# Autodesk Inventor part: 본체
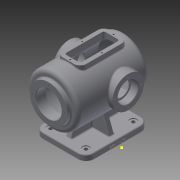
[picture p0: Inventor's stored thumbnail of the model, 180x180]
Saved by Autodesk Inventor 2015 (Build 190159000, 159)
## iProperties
Created: 2021-11
Part Number: 본체
Material: 일반
Document SubType Name: Modeling
Designer: now
Density: 1 g/cm^3
Appearance: 기본값
Author: now
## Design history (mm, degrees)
sketch "스케치1"
  geometry: L1 (-65, 80)-(65, 80); L2 (65, 80)-(65, -80); L3 (65, -80)-(-65, -80); L4 (-65, -80)-(-65, 80); L5 (-65, 80)-(65, -80); L6 (65, 80)-(-65, -80); 1 further point
  constraints: 12 end point, 2 midpoint, 2 parallel, 1 horizontal, 1 perpendicular
  dimensions: "d0" = 130 distance of L2.end L3.end; "d1" = 160 distance of L1.end L2.end
extrude "돌출1" new body sketch "스케치1" distance "d2" = 14; taper "d3" = 0 deg
fillet "모깎기1" dims "d4" = 20
sketch "스케치2"
  geometry: A1 r 20 centre (-45, 60) between (-45, 80) and (-65, 60) reference; A2 r 20 centre (-45, -60) between (-65, -60) and (-45, -80) reference; A3 r 20 centre (45, -60) between (45, -80) and (65, -60) reference; A4 r 20 centre (45, 60) between (65, 60) and (45, 80) reference; 1 further point
hole "구멍1" sketch "스케치2" at (-45, -60), (-45, 60), (45, 60), (45, -60) diameter "d5" = 9; stored, may be unused: countersink angle "d9" = 90 deg, drill point angle "d11" = 118 deg; dims "d6" = 6, "d7" = 18, "d8" = 2, "d10" = 8
fillet "모깎기2" dims "d12" = 3
sketch "스케치3"
  geometry: L1 (-7, -60)-(7, -60); L2 (7, -60)-(7, 60); L3 (7, 60)-(-7, 60); L4 (-7, 60)-(-7, -60); L5 (-7, -60)-(7, 60); L6 (7, -60)-(-7, 60); L7 (-50, 7)-(50, 7); L8 (50, 7)-(50, -7); L9 (50, -7)-(-50, -7); L10 (-50, -7)-(-50, 7); L11 (-50, 7)-(50, -7); L12 (50, 7)-(-50, -7); 1 further point
  constraints: 24 end point, 4 midpoint, 4 parallel, 2 horizontal, 2 perpendicular
  dimensions: "d13" = 120 distance of L1.end L2.end; "d14" = 14 distance of L1.start L1.end; "d15" = 14 distance of L7.end L8.end; "d16" = 100 distance of L8.end L9.end
extrude "돌출2" join sketch "스케치3" distance "d17" = 100; taper "d18" = 0 deg
feature "면 기울기1" dims angle "d19" = 20 deg
feature "면 기울기2" dims angle "d20" = 20 deg
fillet "모깎기3" dims "d21" = 3
fillet "모깎기4" dims "d22" = 3
sketch "스케치4"
  geometry: L1 (62.101, 14)-(77, 14) reference; L2 (80, 11)-(80, 0) reference; L3 (80, 0)-(-80, 0) reference; L4 (-80, 0)-(-80, 11) reference; L5 (-77, 14)-(-62.101, 14) reference; L6 (-59.282, 15.974)-(-23.603, 114) reference; L7 (-23.603, 114)-(23.603, 114) reference; L8 (23.603, 114)-(59.282, 15.974) reference; L9 (100, 114)-(-100, 114); L10 (-100, 114)-(-100, 179); L11 (-100, 179)-(100, 114); L12 (99.021, 184.824)-(-100, 114); L13 (-100, 179)-(75.993, 179); A1 r 3 centre (62.101, 17) between (59.282, 15.974) and (62.101, 14) reference; A2 r 3 centre (77, 11) between (80, 11) and (77, 14) reference; A3 r 3 centre (-77, 11) between (-77, 14) and (-80, 11) reference; A4 r 3 centre (-62.101, 17) between (-62.101, 14) and (-59.282, 15.974) reference; A5 r 100 centre (0, 114) between (100, 114) and (75.993, 179); 2 further points
  constraints: 10 end point, 2 point on circle, 2 point on line, 1 centre point, 1 horizontal
  dimensions: "d23" = 20 distance between parallel lines of L4 L10; "d26" = 114 distance between parallel lines of L9 L3; "d28" = 200 distance from line of L9.start L10; "d37" = 65 distance between parallel lines of L13 L9; "d38" = 175.99342 distance of L10.end L13.end; "d39" = 100 radius of A5
revolve "회전1" sketch "스케치4" stored, may be unused: angle "d32" = 90 deg
sketch "스케치5"
  geometry: C1 r 65 at (0, 0) reference; C2 r 47.5 at (0, 0); 1 further point
  constraints: 1 centre point, 1 coincident
  dimensions: "d33" = 95 diameter of C2
extrude "돌출3" join sketch "스케치5" distance "d34" = 10; taper "d35" = 0 deg
sketch "스케치6"
  geometry: C1 r 47.5 at (0, 0) reference; 1 further point
hole "구멍2" sketch "스케치6" at (0, 0) diameter "d40" = 65; stored, may be unused: countersink angle "d44" = 90 deg, drill point angle "d46" = 0 deg; dims "d41" = 6, "d42" = 4, "d43" = 2, "d45" = 25
chamfer "모따기1" distance "d47" = 1; stored, may be unused: second distance "d48" = 2, angle "d49" = 45 deg
sketch "스케치7"
  geometry: L1 (62.101, 14)-(77, 14) reference; L2 (80, 11)-(80, 0) reference; L3 (80, 0)-(-80, 0) reference; L4 (-80, 0)-(-80, 11) reference; L5 (-77, 14)-(-62.101, 14) reference; L6 (-59.282, 15.974)-(-47.261, 49) reference; L7 (-47.261, 49)-(-100, 49) reference; L8 (-100, 49)-(-100, 66.5) reference; L9 (-100, 66.5)-(-110, 66.5) reference; L10 (-110, 66.5)-(-110, 80.5) reference; L11 (-110, 80.5)-(-109, 81.5) reference; L12 (-109, 81.5)-(-85, 81.5) reference; L13 (-85, 81.5)-(-85, 146.5) reference; L14 (-85, 146.5)-(-109, 146.5) reference; L15 (-109, 146.5)-(-110, 147.5) reference; L16 (-110, 147.5)-(-110, 161.5) reference; L17 (-110, 161.5)-(-100, 161.5) reference; L18 (-100, 161.5)-(-100, 179) reference; L19 (-100, 179)-(75.993, 179) reference; L20 (75.993, 49)-(47.261, 49) reference; L21 (47.261, 49)-(59.282, 15.974) reference; L22 (-85, 169)-(71.239, 169); L23 (-85, 146.5)-(-85, 81.5) reference; L24 (-85, 114)-(90, 114); L25 (-85, 169)-(-85, 114); A1 r 3 centre (62.101, 17) between (59.282, 15.974) and (62.101, 14) reference; A2 r 3 centre (77, 11) between (80, 11) and (77, 14) reference; A3 r 3 centre (-77, 11) between (-77, 14) and (-80, 11) reference; A4 r 3 centre (-62.101, 17) between (-62.101, 14) and (-59.282, 15.974) reference; A5 r 100 centre (0, 114) between (75.993, 49) and (75.993, 179) reference; A6 r 90 centre (0, 114) between (90, 114) and (71.239, 169); 2 further points
  constraints: 6 end point, 2 midpoint, 2 point on circle, 1 centre point, 1 perpendicular, 1 vertical alignment
  dimensions: "d50" = 156.23903 distance of L22.start L22.end; "d51" = 55 distance of L22.start L24.start; "d52" = 175 distance of L24.start L24.end; "d53" = 90 radius of A6
revolve "회전2" sketch "스케치7" stored, may be unused: angle "d54" = 90 deg
fillet "모깎기5" dims "d55" = 3
fillet "모깎기6" dims "d56" = 10
sketch "스케치8"
  geometry: C1 r 47.5 at (0, 0) reference; 2 further points
  constraints: 1 vertical alignment
  dimensions: "d57" = 40 distance of C1.centre point (0, 40)
hole "구멍3" sketch "스케치8" at (0, 40) diameter "d58" = 3.242; stored, may be unused: countersink angle "d62" = 90 deg, drill point angle "d64" = 118 deg; dims "d59" = 11, "d60" = 4, "d61" = 2, "d63" = 13
node "작업 평면1"
sketch "스케치9"
  geometry: L1 (30, -60)-(-30, -60); L2 (-30, -60)-(-30, 60); L3 (-30, 60)-(30, 60); L4 (30, 60)-(30, -60); L5 (30, -60)-(-30, 60); L6 (-30, -60)-(30, 60); L7 (-47.5, -110)-(47.5, -110) reference; 4 further points
  constraints: 12 end point, 4 midpoint, 2 parallel, 1 horizontal, 1 perpendicular, 1 vertical alignment
  dimensions: "d69" = 120 distance of L3.end L1.start; "d70" = 50 distance between parallel lines of L1 L7; "d71" = 60 distance of L1.start L1.end
extrude "돌출4" join sketch "스케치9" stored distance "d72" = 10; taper "d73" = 0 deg
sketch "스케치10"
  geometry: L1 (-20, -50)-(20, -50); L2 (20, -50)-(20, 50); L3 (20, 50)-(-20, 50); L4 (-20, 50)-(-20, -50); 1 further point
  constraints: 8 end point
extrude "돌출5" cut sketch "스케치10" distance "d74" = 47.5; taper "d75" = 0 deg
fillet "모깎기7" dims "d76" = 15
fillet "모깎기8" dims "d77" = 5
fillet "모깎기9" dims "d78" = 3
fillet "모깎기10" dims "d79" = 3
sketch "스케치11"
  geometry: 2 further points
  constraints: 1 horizontal alignment
  dimensions: "d80" = 25 distance of point (-25, 0) point (0, 0)
hole "구멍4" sketch "스케치11" at (-25, 0) diameter "d81" = 3.242; stored, may be unused: countersink angle "d85" = 90 deg, drill point angle "d87" = 118 deg; dims "d82" = 9, "d83" = 4, "d84" = 2, "d86" = 11
sketch "스케치12"
  geometry: 2 further points
  constraints: 1 vertical alignment
  dimensions: "d88" = 55 distance of point (0, 0) point (0, -55)
hole "구멍5" sketch "스케치12" at (0, -55) diameter "d89" = 3.242; stored, may be unused: countersink angle "d93" = 90 deg, drill point angle "d95" = 118 deg; dims "d90" = 9, "d91" = 4, "d92" = 2, "d94" = 11
node "작업 평면2"
node "작업 평면3"
sketch "스케치13"
  geometry: 1 further point
sketch "스케치14"
  geometry: L1 (60, 0)-(-60, 0) reference; C1 r 40 at (17, 114); 1 further point
  constraints: 1 centre point
  dimensions: "d98" = 17 horizontal distance of point (0, 0) C1.centre; "d99" = 80 diameter of C1; "d100" = 114 distance from line of C1.centre L1
extrude "돌출6" join sketch "스케치14" stored distance "d101" = 47.5; taper "d102" = 0 deg
fillet "모깎기11" dims "d103" = 3
sketch "스케치15"
  geometry: C1 r 40 at (0, 0) reference; 1 further point
hole "구멍6" sketch "스케치15" at (0, 0) diameter "d104" = 42; stored, may be unused: countersink angle "d108" = 90 deg, drill point angle "d110" = 0 deg; dims "d105" = 9, "d106" = 52, "d107" = 18, "d109" = 11
sketch "스케치16"
  geometry: C1 r 40 at (0, 0) reference; 1 further point
hole "구멍7" sketch "스케치16" at (0, 0) diameter "d111" = 42; stored, may be unused: countersink angle "d115" = 90 deg, drill point angle "d117" = 0 deg; dims "d112" = 9, "d113" = 52, "d114" = 18, "d116" = 11
fillet "모깎기12" dims "d118" = 0.3
sketch "스케치17"
  geometry: C1 r 26 at (0, 0) reference; 2 further points
  constraints: 1 horizontal alignment
  dimensions: "d119" = 32.5 distance of C1.centre point (-32.5, 0)
hole "구멍8" sketch "스케치17" at (-32.5, 0) diameter "d120" = 3.242; stored, may be unused: countersink angle "d124" = 90 deg, drill point angle "d126" = 118 deg; dims "d121" = 11, "d122" = 52, "d123" = 18, "d125" = 13
chamfer "모따기2" distance "d130" = 1; stored, may be unused: second distance "d131" = 2, angle "d132" = 45 deg
sketch "스케치18"
  geometry: L1 (0, 120)-(0, 0) reference; 3 further points
  constraints: 1 horizontal alignment, 1 midpoint, 1 other
  dimensions: "d133" = 5 distance from line of point (-5, 60) L1
feature "엠보싱1" sketch "스케치18" dims "d134" = 0.5, "d135" = 0
fillet "모깎기13" dims "d136" = 3
fillet "모깎기14" dims "d137" = 3
node "솔리드1"
pattern_circular "원형 패턴1" dims angle "d66" = 360 deg
mirror "대칭1"
mirror "대칭2"
mirror "대칭3"
pattern_circular "원형 패턴2" dims angle "d128" = 360 deg
mirror "대칭4"
node "절단 모서리 투영1"
node "절단 모서리 투영2"
other parameters: "d68" = -184, "d96" = 75, "d97" = 17
